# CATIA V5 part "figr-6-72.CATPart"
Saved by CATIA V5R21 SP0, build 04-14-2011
Part number: Part2
Bounding box of the stored display mesh (mm): x -37.886 to 37.886, y -61.415 to 61.415, z 0 to 29
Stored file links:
  D:\CATIA V5R21 E-RESOURCES\CATIA-V5R21\catia-v5r21-prt\c06-catia-v5r21-prt\c06-catia-v5r21-figr-6-72.CATPart
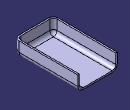
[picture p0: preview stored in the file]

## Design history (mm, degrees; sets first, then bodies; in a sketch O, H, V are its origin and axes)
Body1 (main body)
  Sketch1 on xy-plane, origin (0, 0, 0), H (1, 0, 0), V (0, 1, 0)
    line L1 (37.8862, 61.4155) -> (37.8862, -61.4155)
    line L2 (37.8862, -61.4155) -> (-37.8862, -61.4155)
    line L3 (-37.8862, -61.4155) -> (-37.8862, 61.4155)
    line L4 (-37.8862, 61.4155) -> (37.8862, 61.4155)
    vertical: L1 V, L3 V
    horizontal: L2 H, L4 H
    equidistance: L1 L3 O, L2 L4 O
  Pad1: profile Sketch1, direction (0, 0, 1), length 29
  Fillet1: radius 10, on edge [face of Pad1 | face of Pad1] (x5)
  Shell1: ExtOffset 0, Face (face of Pad1; face of Pad1), IntOffset 3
